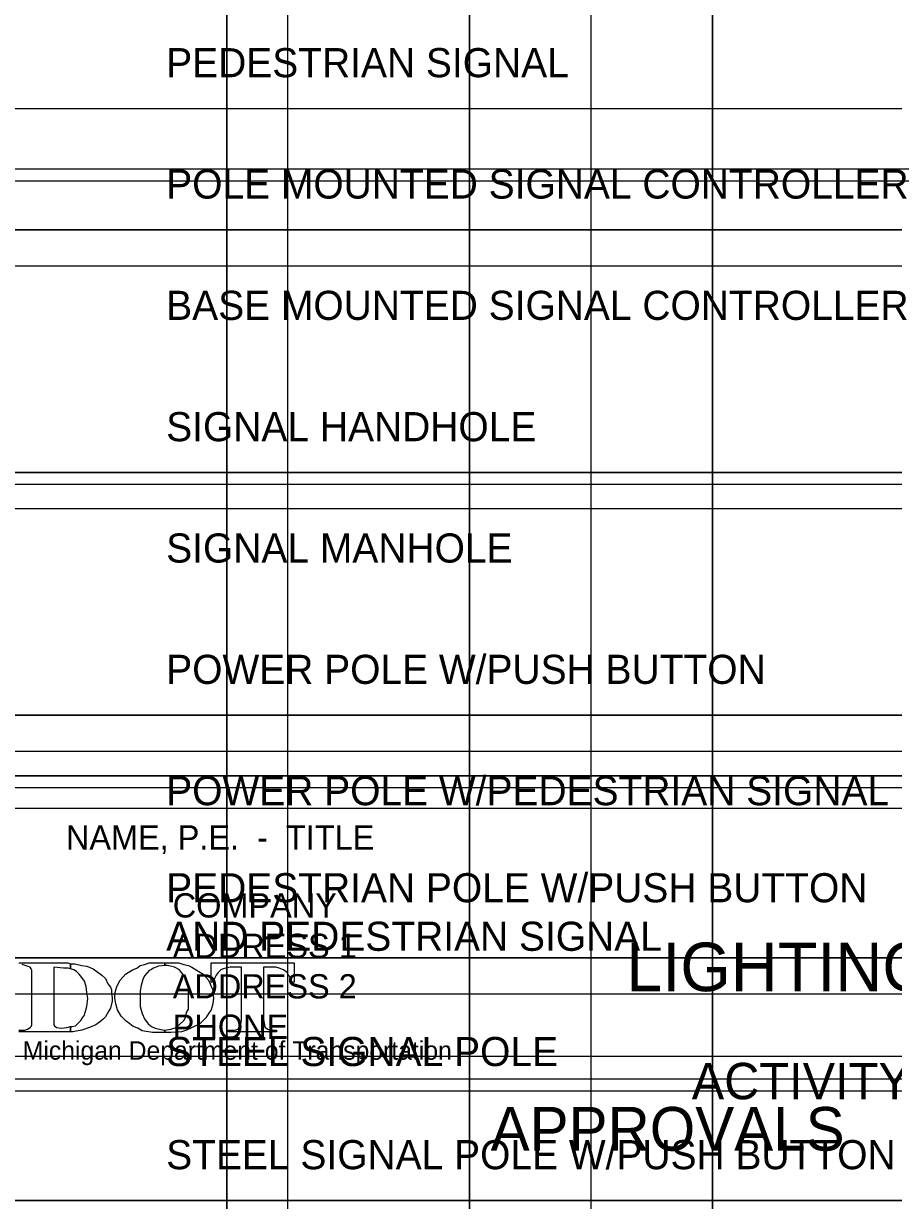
# Model space of a CAD drawing. Extents: x 2146475 to 2147951, y 2147003 to 2148003.
# Drawn here: x 2147619.9 to 2147763.3, y 2147343 to 2147537 of the extents above; entities that cross this region are included whole.
import ezdxf

# ---------------------------------------------------------------- set-up
doc = ezdxf.new("R2010")
doc.units = 0
for name, color, linetype in [('Sheet_Border_Block_LightingInventory', 7, 'Continuous'), ('Sheet_Border_Plan_Dual', 7, 'Continuous'), ('Sheet_Border_PlanOverProf1_Grid+Sta+EL_04_040+08_080', 7, 'Continuous'), ('Sheet_Border_PlanOverProf1_Grid+Sta+EL_10_100+20_200', 7, 'Continuous'), ('Sheet_Border_Prof3_Grid+Sta+EL_04_040+08_080', 7, 'Continuous'), ('Sheet_Border_Prof3_Grid+Sta+EL_10_100+20_200', 7, 'Continuous'), ('Sheet_Border_TitleSheet', 7, 'Continuous'), ('Sheet_Border_TitleSheet_ConsultantBlock', 7, 'Continuous'), ('Sheet_Border_XS_Grid', 7, 'Continuous'), ('Sheet_Label_Misc_Wt1', 7, 'Continuous')]:
    doc.layers.add(name, color=color, linetype=linetype)

msp = doc.modelspace()

# ---------------------------------------------------------------- linework, layer by layer
at = {"layer": 'Sheet_Border_Block_LightingInventory'}
msp.add_line((2147549.81, 2147412.95), (2147871.41, 2147412.95), dxfattribs=at)
for points in [[(2147619.12, 2147382.13), (2147627.19, 2147382.13), (2147627.62, 2147381.98), (2147627.62, 2147381.12), (2147627.19, 2147381.26), (2147626.47, 2147381.26), (2147624.88, 2147381.41), (2147624.88, 2147371.9), (2147625.03, 2147371.76), (2147625.32, 2147371.47), (2147626.18, 2147371.33), (2147627.04, 2147371.47), (2147627.62, 2147371.61), (2147627.62, 2147370.75), (2147619.12, 2147370.75)], [(2147619.12, 2147371.04), (2147620.13, 2147371.04), (2147620.56, 2147371.18), (2147621, 2147371.47), (2147621.14, 2147371.61), (2147621.28, 2147371.9), (2147621.28, 2147380.83), (2147621.14, 2147381.12), (2147621, 2147381.41), (2147619.7, 2147381.84)]]:
    msp.add_lwpolyline(points, dxfattribs=at)
for points in [[(2147643.17, 2147381.69), (2147642.16, 2147381.55), (2147641.3, 2147381.26), (2147640.87, 2147380.97), (2147640.58, 2147380.83), (2147639.86, 2147379.97), (2147639.57, 2147379.39), (2147639.28, 2147378.38), (2147639.14, 2147377.52), (2147639.14, 2147374.93), (2147639.43, 2147373.77), (2147639.86, 2147372.91), (2147640.43, 2147372.05), (2147641.01, 2147371.61), (2147641.59, 2147371.33), (2147643.03, 2147371.04), (2147643.17, 2147371.04), (2147643.17, 2147370.61), (2147641.15, 2147370.61), (2147639.43, 2147370.89), (2147638.71, 2147371.33), (2147637.99, 2147371.61), (2147637.41, 2147372.05), (2147636.83, 2147372.48), (2147635.97, 2147373.34), (2147635.39, 2147374.35), (2147635.11, 2147375.36), (2147634.96, 2147376.37), (2147634.96, 2147376.94), (2147635.11, 2147377.66), (2147635.25, 2147378.24), (2147635.83, 2147379.25), (2147636.69, 2147380.25), (2147637.84, 2147380.97), (2147638.56, 2147381.26), (2147639.14, 2147381.69), (2147639.86, 2147381.84), (2147640.58, 2147382.13), (2147641.3, 2147382.13), (2147643.17, 2147382.13)], [(2147644.18, 2147371.18), (2147645.04, 2147371.47), (2147646.34, 2147372.62), (2147646.63, 2147373.2), (2147646.77, 2147373.92), (2147647.06, 2147374.49), (2147647.06, 2147378.24), (2147646.77, 2147378.96), (2147646.63, 2147379.53), (2147646.34, 2147380.11), (2147645.91, 2147380.54), (2147645.62, 2147380.97), (2147644.75, 2147381.41), (2147643.6, 2147381.69), (2147643.17, 2147381.69), (2147643.17, 2147382.13), (2147644.75, 2147382.13), (2147645.47, 2147382.13), (2147646.34, 2147381.84), (2147647.06, 2147381.69), (2147647.63, 2147381.41), (2147648.35, 2147380.97), (2147649.51, 2147380.25), (2147650.37, 2147379.25), (2147650.66, 2147378.67), (2147650.8, 2147378.24), (2147651.09, 2147377.66), (2147651.09, 2147376.94), (2147651.23, 2147376.37), (2147651.09, 2147375.36), (2147650.8, 2147374.35), (2147650.51, 2147373.92), (2147650.23, 2147373.49), (2147649.94, 2147373.05), (2147648.93, 2147372.05), (2147647.49, 2147371.33), (2147646.77, 2147371.04), (2147645.91, 2147370.75), (2147644.18, 2147370.61), (2147643.17, 2147370.61), (2147643.17, 2147371.04)], [(2147650.8, 2147382.13), (2147664.48, 2147382.13), (2147664.48, 2147378.96), (2147664.05, 2147378.96), (2147663.91, 2147379.53), (2147663.76, 2147379.82), (2147663.47, 2147380.25), (2147663.33, 2147380.54), (2147662.75, 2147380.97), (2147662.03, 2147381.26), (2147661.46, 2147381.41), (2147659.44, 2147381.41), (2147659.44, 2147372.77), (2147659.59, 2147371.9), (2147659.59, 2147371.61), (2147659.73, 2147371.47), (2147660.16, 2147371.18), (2147660.59, 2147371.04), (2147661.6, 2147371.04), (2147661.6, 2147370.75), (2147653.68, 2147370.75), (2147653.68, 2147371.04), (2147654.69, 2147371.04), (2147655.27, 2147371.18), (2147655.41, 2147371.47), (2147655.7, 2147371.61), (2147655.7, 2147371.9), (2147655.84, 2147372.77), (2147655.84, 2147381.41), (2147653.97, 2147381.41), (2147652.82, 2147381.12), (2147652.39, 2147380.97), (2147651.95, 2147380.54), (2147651.67, 2147380.11), (2147651.38, 2147379.53), (2147651.23, 2147378.96), (2147650.8, 2147378.96)], [(2147627.91, 2147371.61), (2147628.48, 2147371.76), (2147629.35, 2147372.62), (2147629.63, 2147373.05), (2147629.92, 2147373.49), (2147630.07, 2147373.92), (2147630.35, 2147374.93), (2147630.5, 2147376.22), (2147630.35, 2147377.23), (2147630.21, 2147378.24), (2147629.92, 2147379.1), (2147629.49, 2147379.68), (2147629.06, 2147380.25), (2147628.63, 2147380.69), (2147628.2, 2147380.97), (2147627.62, 2147381.12), (2147627.62, 2147381.98), (2147628.34, 2147381.98), (2147629.49, 2147381.69), (2147630.35, 2147381.55), (2147631.36, 2147381.12), (2147632.8, 2147380.11), (2147633.38, 2147379.53), (2147633.81, 2147378.67), (2147634.24, 2147378.09), (2147634.39, 2147377.66), (2147634.39, 2147377.09), (2147634.53, 2147376.37), (2147634.53, 2147375.79), (2147634.24, 2147374.64), (2147633.95, 2147374.21), (2147633.38, 2147373.2), (2147633.09, 2147372.91), (2147632.66, 2147372.48), (2147631.79, 2147371.9), (2147630.79, 2147371.47), (2147629.49, 2147371.04), (2147628.05, 2147370.75), (2147627.62, 2147370.75), (2147627.62, 2147371.61)]]:
    msp.add_lwpolyline(points, close=True, dxfattribs=at)
at = {"layer": 'Sheet_Border_Plan_Dual'}
msp.add_line((2146555.41, 2147522.95), (2147871.41, 2147522.95), dxfattribs=at)
at = {"layer": 'Sheet_Border_PlanOverProf1_Grid+Sta+EL_04_040+08_080'}
for p, q in [((2146555.41, 2147522.95), (2147871.41, 2147522.95)), ((2147813.41, 2147512.95), (2146613.41, 2147512.95)), ((2147663.41, 2147512.95), (2147663.41, 2147138.95)), ((2147713.41, 2147512.95), (2147713.41, 2147138.95)), ((2147813.41, 2147462.95), (2146613.41, 2147462.95)), ((2147813.41, 2147412.95), (2146613.41, 2147412.95)), ((2147813.41, 2147362.95), (2146613.41, 2147362.95))]:
    msp.add_line(p, q, dxfattribs=at)
at = {"layer": 'Sheet_Border_PlanOverProf1_Grid+Sta+EL_10_100+20_200'}
for p, q in [((2146555.41, 2147522.95), (2147871.41, 2147522.95)), ((2147813.41, 2147502.95), (2146613.41, 2147502.95)), ((2147653.41, 2147502.95), (2147653.41, 2147158.95)), ((2147693.41, 2147502.95), (2147693.41, 2147158.95)), ((2147733.41, 2147502.95), (2147733.41, 2147158.95)), ((2147813.41, 2147462.95), (2146613.41, 2147462.95)), ((2147813.41, 2147422.95), (2146613.41, 2147422.95)), ((2147813.41, 2147382.95), (2146613.41, 2147382.95)), ((2147813.41, 2147342.95), (2146613.41, 2147342.95))]:
    msp.add_line(p, q, dxfattribs=at)
at = {"layer": 'Sheet_Border_Prof3_Grid+Sta+EL_04_040+08_080'}
for p, q in [((2147663.41, 2147910.95), (2147663.41, 2147136.95)), ((2147713.41, 2147910.95), (2147713.41, 2147136.95)), ((2147813.41, 2147510.95), (2146613.41, 2147510.95)), ((2147813.41, 2147460.95), (2146613.41, 2147460.95)), ((2147813.41, 2147410.95), (2146613.41, 2147410.95)), ((2147813.41, 2147360.95), (2146613.41, 2147360.95))]:
    msp.add_line(p, q, dxfattribs=at)
at = {"layer": 'Sheet_Border_Prof3_Grid+Sta+EL_10_100+20_200'}
for p, q in [((2147653.41, 2147896.95), (2147653.41, 2147152.95)), ((2147693.41, 2147896.95), (2147693.41, 2147152.95)), ((2147733.41, 2147896.95), (2147733.41, 2147152.95)), ((2147813.41, 2147496.95), (2146613.41, 2147496.95)), ((2147813.41, 2147456.95), (2146613.41, 2147456.95)), ((2147813.41, 2147416.95), (2146613.41, 2147416.95)), ((2147813.41, 2147376.95), (2146613.41, 2147376.95))]:
    msp.add_line(p, q, dxfattribs=at)
at = {"layer": 'Sheet_Border_TitleSheet'}
msp.add_line((2147571.41, 2147366.72), (2147871.41, 2147366.72), dxfattribs=at)
at = {"layer": 'Sheet_Border_TitleSheet_ConsultantBlock'}
msp.add_line((2147603.25, 2147407.59), (2147769.16, 2147407.59), dxfattribs=at)
at = {"layer": 'Sheet_Border_XS_Grid'}
for p, q in [((2147653.41, 2147142.95), (2147653.41, 2147902.95)), ((2147693.41, 2147142.95), (2147693.41, 2147902.95)), ((2147733.41, 2147142.95), (2147733.41, 2147902.95)), ((2146573.41, 2147502.95), (2147853.41, 2147502.95)), ((2146573.41, 2147462.95), (2147853.41, 2147462.95)), ((2146573.41, 2147422.95), (2147853.41, 2147422.95)), ((2146573.41, 2147382.95), (2147853.41, 2147382.95)), ((2146573.41, 2147342.95), (2147853.41, 2147342.95))]:
    msp.add_line(p, q, dxfattribs=at)

# ---------------------------------------------------------------- texts
at = {"layer": 'Sheet_Border_Block_LightingInventory'}
for s, height, p in [('LIGHTING INVENTORY', 7.9998, (2147719.21, 2147377.45)), ('ACTIVITY CODE 135', 6, (2147730.01, 2147359.63))]:
    msp.add_text(s, height=height, dxfattribs=at).set_placement(p)
msp.add_text('Michigan Department of Transportation', height=3.0492, rotation=360, dxfattribs=at).set_placement((2147619.77, 2147366.15))
at = {"layer": 'Sheet_Border_TitleSheet'}
msp.add_text('APPROVALS', height=7.2, dxfattribs=at).set_placement((2147696.88, 2147351.16))
at = {"layer": 'Sheet_Border_TitleSheet_ConsultantBlock'}
for s, p in [('                NAME, P.E.  -  TITLE               ', (2147603.11, 2147400.79)), ('COMPANY                       ', (2147644.49, 2147389.59)), ('ADDRESS 1                     ', (2147644.49, 2147382.92)), ('ADDRESS 2                     ', (2147644.49, 2147376.25)), ('PHONE                         ', (2147644.49, 2147369.59))]:
    msp.add_text(s, height=4, dxfattribs=at).set_placement(p)
at = {"layer": 'Sheet_Label_Misc_Wt1'}
for s, p in [('PEDESTRIAN SIGNAL', (2147643.41, 2147528.1)), ('POLE MOUNTED SIGNAL CONTROLLER', (2147643.41, 2147508.1)), ('BASE MOUNTED SIGNAL CONTROLLER', (2147643.41, 2147488.1)), ('SIGNAL HANDHOLE', (2147643.41, 2147468.1)), ('SIGNAL MANHOLE', (2147643.41, 2147448.1)), ('POWER POLE W/PUSH BUTTON', (2147643.41, 2147428.1)), ('POWER POLE W/PEDESTRIAN SIGNAL', (2147643.41, 2147408.1)), ('PEDESTRIAN POLE W/PUSH BUTTON', (2147643.41, 2147392.1)), ('AND PEDESTRIAN SIGNAL', (2147643.41, 2147384.1)), ('STEEL SIGNAL POLE ', (2147643.41, 2147365.1)), ('STEEL SIGNAL POLE W/PUSH BUTTON', (2147643.41, 2147348.1))]:
    msp.add_text(s, height=4.8, dxfattribs=at).set_placement(p)

doc.saveas('drawing.dxf')
